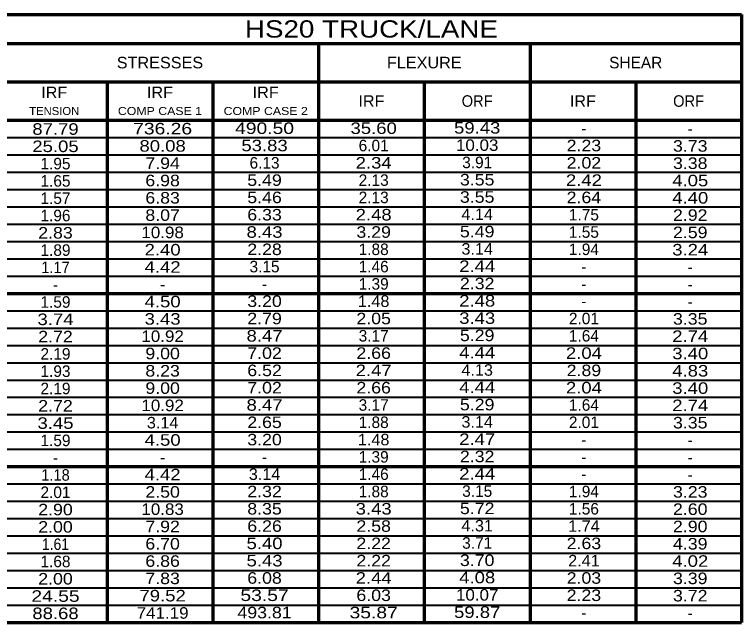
# Model space of a CAD drawing. Extents: x -2055 to -1915, y -81 to 6.
# Drawn here: x -1961.57 to -1923.75, y -25.85 to 5.78 of the extents above; entities that cross this region are included whole.
import ezdxf
from ezdxf.enums import TextEntityAlignment as Align

# ---------------------------------------------------------------- set-up
doc = ezdxf.new("R2010")
doc.units = 0
doc.header["$LTSCALE"] = 0.24
doc.layers.add('1', color=7, linetype='Continuous', lineweight=70)
doc.layers.add('5', color=7, linetype='Continuous', lineweight=40)
doc.layers.add('21', color=7, linetype='Continuous')
doc.layers.add('9', color=7, linetype='Continuous')

msp = doc.modelspace()

# ---------------------------------------------------------------- linework, layer by layer
at = {"layer": '1'}
for p, q in [((-2009.7523, 5.7798), (-1923.7523, 5.7798)), ((-1923.7523, 5.7798), (-1923.7523, -25.8503)), ((-2009.7523, 4.2798), (-1923.7523, 4.2798)), ((-1945.7523, 4.2798), (-1945.7523, -25.8503)), ((-1934.7523, 4.2798), (-1934.7523, -25.8503)), ((-2000.7523, 2.2798), (-1923.7523, 2.2798)), ((-1956.7523, 2.2798), (-1956.7523, -25.8503)), ((-1951.2523, 2.2798), (-1951.2523, -25.8503)), ((-1940.2523, 2.2798), (-1940.2523, -25.8503)), ((-1929.2523, 2.2798), (-1929.2523, -25.8503)), ((-2009.7523, 0.2798), (-1923.7523, 0.2798)), ((-2009.7523, -8.7306), (-1923.7523, -8.7306)), ((-2009.7523, -17.741), (-1923.7523, -17.741)), ((-2009.7523, -25.8503), (-1923.7523, -25.8503))]:
    msp.add_line(p, q, dxfattribs=at)
at = {"layer": '5'}
for p, q in [((-2005.7523, -0.6212), (-1923.7523, -0.6212)), ((-2005.7523, -1.5222), (-1923.7523, -1.5222)), ((-2005.7523, -2.4232), (-1923.7523, -2.4232)), ((-2005.7523, -3.3243), (-1923.7523, -3.3243)), ((-2005.7523, -4.2253), (-1923.7523, -4.2253)), ((-2005.7523, -5.1264), (-1923.7523, -5.1264)), ((-2005.7523, -6.0274), (-1923.7523, -6.0274)), ((-2005.7523, -6.9285), (-1923.7523, -6.9285)), ((-2005.7523, -7.8295), (-1923.7523, -7.8295)), ((-2005.7523, -9.6316), (-1923.7523, -9.6316)), ((-2005.7523, -10.5327), (-1923.7523, -10.5327)), ((-2005.7523, -11.4337), (-1923.7523, -11.4337)), ((-2005.7523, -12.3347), (-1923.7523, -12.3347)), ((-2005.7523, -13.2357), (-1923.7523, -13.2357)), ((-2005.7523, -14.1368), (-1923.7523, -14.1368)), ((-2005.7523, -15.0378), (-1923.7523, -15.0378)), ((-2005.7523, -15.9389), (-1923.7523, -15.9389)), ((-2005.7523, -16.8399), (-1923.7523, -16.8399)), ((-2005.7523, -18.642), (-1923.7523, -18.642)), ((-2005.7523, -19.5431), (-1923.7523, -19.5431)), ((-2005.7523, -20.4441), (-1923.7523, -20.4441)), ((-2005.7523, -21.3452), (-1923.7523, -21.3452)), ((-2005.7523, -22.2462), (-1923.7523, -22.2462)), ((-2005.7523, -23.1472), (-1923.7523, -23.1472)), ((-2005.7523, -24.0482), (-1923.7523, -24.0482)), ((-2005.7523, -24.9493), (-1923.7523, -24.9493))]:
    msp.add_line(p, q, dxfattribs=at)

# ---------------------------------------------------------------- texts
at = {"layer": '21'}
for s, height, width, p in [('STRESSES', 0.6, 1.05, (-1954.0022, 2.9798)), ('FLEXURE', 0.6, 1.05, (-1940.2521, 2.9798)), ('IRF', 0.6, 1.05, (-1959.5021, 1.4298)), ('IRF', 0.6, 1.05, (-1954.0021, 1.4298)), ('IRF', 0.6, 1.05, (-1948.5021, 1.4298)), ('IRF', 0.6, 1.05, (-1943.0021, 0.9798)), ('ORF', 0.6, 0.95, (-1937.5022, 0.9798)), ('IRF', 0.6, 1.05, (-1932.0021, 0.9798)), ('ORF', 0.6, 0.95, (-1926.5022, 0.9798)), ('TENSION', 0.4167, 1.05, (-1959.5022, 0.5525)), ('COMP CASE 1', 0.4167, 1.15, (-1954.0022, 0.5525)), ('COMP CASE 2', 0.4167, 1.15, (-1948.5023, 0.5525))]:
    msp.add_text(s, height=height, dxfattribs=dict(at, width=width)).set_placement(p, align=Align.CENTER)
msp.add_text('SHEAR', height=0.6, dxfattribs=at).set_placement((-1929.2522, 2.9798), align=Align.CENTER)
at = {"layer": '9'}
for s, height, width, p in [('HS20 TRUCK/LANE', 0.9, 1.2, (-1943.0018, 4.5798)), ('87.79', 0.6, 1.2, (-1959.437, -0.4763)), ('736.26', 0.6, 1.25, (-1953.8642, -0.4555)), ('490.50', 0.6, 1.25, (-1948.5618, -0.4347)), ('35.60', 0.6, 1.2, (-1942.8852, -0.4347)), ('59.43', 0.6, 1.2, (-1937.4996, -0.4139)), ('80.08', 0.6, 1.2, (-1953.8642, -1.3555)), ('53.83', 0.6, 1.2, (-1948.5619, -1.3347)), ('10.03', 0.6, 1.1, (-1937.4996, -1.3139)), ('2.23', 0.6, 1.15, (-1931.9477, -1.3347)), ('3.73', 0.6, 1.15, (-1926.4166, -1.3555)), ('25.05', 0.6, 1.2, (-1959.4369, -1.3763)), ('7.94', 0.6, 1.15, (-1953.8642, -2.2555)), ('2.34', 0.6, 1.2, (-1942.8852, -2.2348)), ('2.02', 0.6, 1.15, (-1931.9477, -2.2348)), ('3.38', 0.6, 1.15, (-1926.4166, -2.2555)), ('6.98', 0.6, 1.15, (-1953.8643, -3.1555)), ('5.49', 0.6, 1.15, (-1948.5619, -3.1347)), ('3.55', 0.6, 1.15, (-1937.4996, -3.1139)), ('2.42', 0.6, 1.2, (-1931.9477, -3.1347)), ('4.05', 0.6, 1.2, (-1926.4166, -3.1555)), ('6.83', 0.6, 1.15, (-1953.8642, -4.0555)), ('5.46', 0.6, 1.15, (-1948.5619, -4.0347)), ('3.55', 0.6, 1.15, (-1937.4996, -4.0139)), ('2.64', 0.6, 1.15, (-1931.9477, -4.0347)), ('4.40', 0.6, 1.2, (-1926.4166, -4.0555)), ('8.07', 0.6, 1.15, (-1953.8642, -4.9555)), ('6.33', 0.6, 1.15, (-1948.5618, -4.9348)), ('2.48', 0.6, 1.2, (-1942.8852, -4.9348)), ('4.14', 0.6, 1.05, (-1937.4996, -4.9139)), ('2.92', 0.6, 1.15, (-1926.4166, -4.9555)), ('2.83', 0.6, 1.15, (-1959.437, -5.8763)), ('10.98', 0.6, 1.1, (-1953.8642, -5.8555)), ('8.43', 0.6, 1.2, (-1948.5619, -5.8347)), ('3.29', 0.6, 1.15, (-1942.8852, -5.8347)), ('5.49', 0.6, 1.15, (-1937.4996, -5.8139)), ('2.59', 0.6, 1.15, (-1926.4166, -5.8555)), ('2.40', 0.6, 1.2, (-1953.8642, -6.7555)), ('2.28', 0.6, 1.15, (-1948.5619, -6.7348)), ('3.14', 0.6, 1.05, (-1937.4996, -6.7139)), ('3.24', 0.6, 1.2, (-1926.4166, -6.7555)), ('1.17', 0.6, 0.95, (-1959.4369, -7.6763)), ('4.42', 0.6, 1.2, (-1953.8643, -7.6555)), ('2.44', 0.6, 1.2, (-1937.4996, -7.6139)), ('2.32', 0.6, 1.15, (-1937.4996, -8.5139)), ('4.50', 0.6, 1.2, (-1953.8642, -9.4555)), ('3.20', 0.6, 1.15, (-1948.5618, -9.4347)), ('1.48', 0.6, 1.05, (-1942.8852, -9.4347)), ('2.48', 0.6, 1.2, (-1937.4996, -9.4139)), ('3.74', 0.6, 1.2, (-1959.437, -10.3763)), ('3.43', 0.6, 1.2, (-1953.8643, -10.3555)), ('2.79', 0.6, 1.15, (-1948.5619, -10.3347)), ('2.05', 0.6, 1.15, (-1942.8852, -10.3347)), ('3.43', 0.6, 1.2, (-1937.4996, -10.3139)), ('3.35', 0.6, 1.15, (-1926.4166, -10.3555)), ('2.72', 0.6, 1.15, (-1959.437, -11.2763)), ('10.92', 0.6, 1.1, (-1953.8642, -11.2555)), ('8.47', 0.6, 1.2, (-1948.5619, -11.2348)), ('5.29', 0.6, 1.15, (-1937.4996, -11.2139)), ('2.74', 0.6, 1.2, (-1926.4166, -11.2555)), ('9.00', 0.6, 1.15, (-1953.8642, -12.1555)), ('7.02', 0.6, 1.15, (-1948.5618, -12.1348)), ('2.66', 0.6, 1.15, (-1942.8852, -12.1348)), ('4.44', 0.6, 1.2, (-1937.4996, -12.1139)), ('2.04', 0.6, 1.2, (-1931.9477, -12.1348)), ('3.40', 0.6, 1.2, (-1926.4166, -12.1555)), ('8.23', 0.6, 1.15, (-1953.8643, -13.0555)), ('6.52', 0.6, 1.15, (-1948.5618, -13.0347)), ('2.47', 0.6, 1.2, (-1942.8852, -13.0347)), ('4.13', 0.6, 1.05, (-1937.4996, -13.0139)), ('2.89', 0.6, 1.15, (-1931.9477, -13.0347)), ('4.83', 0.6, 1.2, (-1926.4166, -13.0555)), ('9.00', 0.6, 1.15, (-1953.8642, -13.9555)), ('7.02', 0.6, 1.15, (-1948.5618, -13.9347)), ('2.66', 0.6, 1.15, (-1942.8852, -13.9347)), ('4.44', 0.6, 1.2, (-1937.4996, -13.9139)), ('2.04', 0.6, 1.2, (-1931.9477, -13.9347)), ('3.40', 0.6, 1.2, (-1926.4166, -13.9555)), ('2.72', 0.6, 1.15, (-1959.437, -14.8763)), ('10.92', 0.6, 1.1, (-1953.8642, -14.8555)), ('8.47', 0.6, 1.2, (-1948.5619, -14.8347)), ('5.29', 0.6, 1.15, (-1937.4996, -14.8139)), ('2.74', 0.6, 1.2, (-1926.4166, -14.8555)), ('2.65', 0.6, 1.15, (-1948.5618, -15.7348)), ('3.14', 0.6, 1.05, (-1937.4996, -15.7139)), ('3.45', 0.6, 1.2, (-1959.437, -15.7763)), ('3.14', 0.6, 1.05, (-1953.8642, -15.7555)), ('3.35', 0.6, 1.15, (-1926.4166, -15.7555)), ('4.50', 0.6, 1.2, (-1953.8642, -16.6555)), ('3.20', 0.6, 1.15, (-1948.5618, -16.6348)), ('1.48', 0.6, 1.05, (-1942.8852, -16.6348)), ('2.47', 0.6, 1.2, (-1937.4996, -16.6139)), ('2.32', 0.6, 1.15, (-1937.4996, -17.5139)), ('1.18', 0.6, 0.95, (-1959.4369, -18.4763)), ('4.42', 0.6, 1.2, (-1953.8643, -18.4555)), ('3.14', 0.6, 1.05, (-1948.5618, -18.4348)), ('2.44', 0.6, 1.2, (-1937.4996, -18.4139)), ('2.50', 0.6, 1.15, (-1953.8642, -19.3555)), ('2.32', 0.6, 1.15, (-1948.5619, -19.3347)), ('3.23', 0.6, 1.15, (-1926.4166, -19.3555)), ('10.83', 0.6, 1.1, (-1953.8642, -20.2555)), ('8.35', 0.6, 1.15, (-1948.5619, -20.2347)), ('3.43', 0.6, 1.2, (-1942.8852, -20.2347)), ('5.72', 0.6, 1.15, (-1937.4996, -20.2139)), ('2.60', 0.6, 1.15, (-1926.4166, -20.2555)), ('2.90', 0.6, 1.15, (-1959.437, -20.2763)), ('2.00', 0.6, 1.15, (-1959.4369, -21.1763)), ('7.92', 0.6, 1.15, (-1953.8642, -21.1555)), ('6.26', 0.6, 1.15, (-1948.5618, -21.1348)), ('2.58', 0.6, 1.15, (-1942.8852, -21.1348)), ('4.31', 0.6, 1.05, (-1937.4996, -21.1139)), ('1.74', 0.6, 1.05, (-1931.9477, -21.1348)), ('2.90', 0.6, 1.15, (-1926.4166, -21.1555)), ('1.61', 0.6, 0.9, (-1959.437, -22.0763)), ('6.70', 0.6, 1.15, (-1953.8643, -22.0555)), ('5.40', 0.6, 1.2, (-1948.5618, -22.0347)), ('2.22', 0.6, 1.15, (-1942.8852, -22.0347)), ('2.63', 0.6, 1.15, (-1931.9477, -22.0347)), ('4.39', 0.6, 1.15, (-1926.4166, -22.0555)), ('3.70', 0.6, 1.15, (-1937.4996, -22.9139)), ('6.86', 0.6, 1.15, (-1953.8642, -22.9555)), ('5.43', 0.6, 1.2, (-1948.5619, -22.9347)), ('2.22', 0.6, 1.15, (-1942.8852, -22.9347)), ('2.41', 0.6, 1.05, (-1931.9477, -22.9347)), ('4.02', 0.6, 1.2, (-1926.4166, -22.9555)), ('2.00', 0.6, 1.15, (-1959.4369, -23.8763)), ('7.83', 0.6, 1.15, (-1953.8643, -23.8555)), ('6.08', 0.6, 1.15, (-1948.5619, -23.8347)), ('2.44', 0.6, 1.2, (-1942.8852, -23.8347)), ('4.08', 0.6, 1.2, (-1937.4996, -23.8139)), ('2.03', 0.6, 1.15, (-1931.9477, -23.8347)), ('3.39', 0.6, 1.15, (-1926.4166, -23.8555)), ('24.55', 0.6, 1.25, (-1959.437, -24.7763)), ('79.52', 0.6, 1.2, (-1953.8642, -24.7555)), ('53.57', 0.6, 1.25, (-1948.5619, -24.7347)), ('6.03', 0.6, 1.15, (-1942.8852, -24.7347)), ('10.07', 0.6, 1.1, (-1937.4996, -24.7139)), ('2.23', 0.6, 1.15, (-1931.9477, -24.7347)), ('3.72', 0.6, 1.15, (-1926.4166, -24.7555)), ('88.68', 0.6, 1.2, (-1959.4369, -25.6763)), ('741.19', 0.6, 1.1, (-1953.8642, -25.6555)), ('493.81', 0.6, 1.15, (-1948.5618, -25.6348)), ('35.87', 0.6, 1.25, (-1942.8852, -25.6348)), ('59.87', 0.6, 1.2, (-1937.4996, -25.6139))]:
    msp.add_text(s, height=height, dxfattribs=dict(at, width=width)).set_placement(p, align=Align.CENTER)
for s, p in [('-', (-1931.9477, -0.4347)), ('-', (-1926.4166, -0.4555)), ('6.01', (-1942.8852, -1.3347)), ('1.95', (-1959.4369, -2.2763)), ('6.13', (-1948.5618, -2.2348)), ('3.91', (-1937.4996, -2.2139)), ('1.65', (-1959.4369, -3.1763)), ('2.13', (-1942.8852, -3.1347)), ('1.57', (-1959.4369, -4.0763)), ('2.13', (-1942.8852, -4.0347)), ('1.96', (-1959.4369, -4.9763)), ('1.75', (-1931.9477, -4.9348)), ('1.55', (-1931.9477, -5.8347)), ('1.89', (-1959.437, -6.7763)), ('1.88', (-1942.8852, -6.7348)), ('1.94', (-1931.9477, -6.7348)), ('3.15', (-1948.5619, -7.6347)), ('1.46', (-1942.8852, -7.6347)), ('-', (-1931.9477, -7.6347)), ('-', (-1926.4166, -7.6555)), ('1.39', (-1942.8852, -8.5347)), ('-', (-1959.437, -8.5763)), ('-', (-1953.8642, -8.5555)), ('-', (-1948.5619, -8.5347)), ('-', (-1931.9477, -8.5347)), ('-', (-1926.4166, -8.5555)), ('1.59', (-1959.437, -9.4763)), ('-', (-1931.9477, -9.4347)), ('-', (-1926.4166, -9.4555)), ('2.01', (-1931.9477, -10.3347)), ('3.17', (-1942.8852, -11.2348)), ('1.64', (-1931.9477, -11.2348)), ('2.19', (-1959.437, -12.1763)), ('1.93', (-1959.4369, -13.0763)), ('2.19', (-1959.437, -13.9763)), ('3.17', (-1942.8852, -14.8347)), ('1.64', (-1931.9477, -14.8347)), ('1.88', (-1942.8852, -15.7348)), ('2.01', (-1931.9477, -15.7348)), ('1.59', (-1959.437, -16.6763)), ('-', (-1931.9477, -16.6348)), ('-', (-1926.4166, -16.6555)), ('1.39', (-1942.8852, -17.5347)), ('-', (-1959.437, -17.5763)), ('-', (-1953.8642, -17.5555)), ('-', (-1948.5619, -17.5347)), ('-', (-1931.9477, -17.5347)), ('-', (-1926.4166, -17.5555)), ('1.46', (-1942.8852, -18.4348)), ('-', (-1931.9477, -18.4348)), ('-', (-1926.4166, -18.4555)), ('2.01', (-1959.4369, -19.3763)), ('1.88', (-1942.8852, -19.3347)), ('3.15', (-1937.4996, -19.3139)), ('1.94', (-1931.9477, -19.3347)), ('1.56', (-1931.9477, -20.2347)), ('3.71', (-1937.4996, -22.0139)), ('1.68', (-1959.4369, -22.9763)), ('-', (-1931.9477, -25.6348)), ('-', (-1926.4166, -25.6555))]:
    msp.add_text(s, height=0.6, dxfattribs=at).set_placement(p, align=Align.CENTER)

doc.saveas('drawing.dxf')
